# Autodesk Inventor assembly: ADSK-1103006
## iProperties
Shininess: 50.0
Length Units: 11272
Angle Units: 11279
Time Units: 11290
Mass Units: 11286
Length Display Precision: 4
Angle Display Precision: 2
Compacted: True
Created: 2000-08
Part Number: ADSK-1103006
Document SubType Name: Assembly
Description: ENGINE EXHAUST - SIDE
Mass: 3.92359 g
Surface Area: 74.2294 cm^2
Volume: 3.92359 cm^3
Density: 1 g/cm^3
Density: 0.0
Volumn: 0.0
Area: 0.0
PropertySet Name: Model Information
Control State: 0
Master: False
Checked Out: False
